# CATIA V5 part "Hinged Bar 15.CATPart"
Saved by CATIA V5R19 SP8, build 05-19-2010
Part number: Hinged Bar 15
Bounding box of the stored display mesh (mm): x -28 to 28, y 589.195 to 1010.805, z 490.09 to 709.91
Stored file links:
  G:\EU_thinkMotion\CFAO_2010\MMS_groupe3\MMS_groupe3\A reprendre\fovide\fovide\Hinged Bar 15.CATPart
  G:\EU_thinkMotion\CFAO_2010\MMS_groupe3\MMS_groupe3\A reprendre\fovide\fovide\fovide.CATProduct
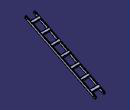
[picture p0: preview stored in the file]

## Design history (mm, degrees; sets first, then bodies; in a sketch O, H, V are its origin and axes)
Parameters
  LENGTH = 50 mm
  LENGTH = 15 mm
Set1
  Plane1: linked copy from another document
  Line1 to Line3: linked copy from another document
Body1 (main body)
  Sketch1 on Plane1, origin (0, 400, 800), H (-1, 0, 0), V (0, -0.8944, 0.4472)
    line L1 (22, -213.6068) -> (28, -213.6068)
    line L2 (28, -213.6068) -> (28, -680.8204)
    line L3 (22, -242.8758) -> (22, -213.6068)
    point P5 (-28, -213.6068)
    line L4 (-28, -213.6068) -> (-22, -213.6068)
    line L5 (-22, -213.6068) -> (-22, -242.8758)
    line L6 (-28, -680.8204) -> (-28, -213.6068)
    reference projected line E1 (150, -223.6068) -> (-150, -223.6068) from Line1
    reference projected line E2 (0, -223.6068) -> (0, -670.8204) from Line2
    reference projected line E3 (0, -223.6068) -> (0, -670.8204) from Line2
    line L7 (-22, -242.8758) -> (22, -242.8758)
    line L8 (28, -680.8204) -> (22, -680.8204)
    point P9 (22, -680.8204)
    line L9 (22, -680.8204) -> (22, -650.0266)
    line L10 (-28, -680.8204) -> (-22, -680.8204)
    point P11 (-22, -680.8204)
    line L11 (-22, -650.0266) -> (22, -650.0266)
    line L12 (-22, -650.0266) -> (-22, -680.8204)
    reference projected line E4 (150, -670.8204) -> (-150, -670.8204) from Line3
    length L1 = 6
    length L4 = 6
    distance L1 E1 = 10
    distance E2 L3 = 22
    distance E3 L5 = 22
    distance L8 E4 = 10
    horizontal: L1 H, L4 H, L7 H, L8 H, L10 H, L11 H
    vertical: L2 V, L3 V, L5 V, L6 V, L9 V, L12 V
    coincidence: P5 L1, P9 L3, P11 L5, L10 L8
  Pad1: profile Sketch1, direction (0, 0.4472, 0.8944), length 8, mirrored extent
  Sketch2 on face of Pad1 from Sketch1.L6, origin (28, 600, 700), H (0, 1, 0), V (0, 0, 1)
    point P1 (0, 0)
    intersected point E1 (0, 0) from Line1
    coincidence: E1 P1
  Hole1: placed by Sketch2, at (28, 600, 700) direction (-1, 0, 0), diameter 10, through (limit type 3)
  Sketch3 on face of Pad1 from Sketch1.L6, origin (28, 1000, 500), H (0, 1, 0), V (0, 0, 1)
    point P1 (0, 0)
    intersected point E1 (0, 0) from Line3
    coincidence: E1 P1
  Hole2: placed by Sketch3, at (28, 1000, 500) direction (-1, 0, 0), diameter 10, through (limit type 3)
  Sketch4 on end face of Pad1, origin (0, 403.5777, 807.1554), H (-1, 0, 0), V (0, -0.8944, 0.4472)
    line L1 (-22, -258.3758) -> (22, -258.3758)
    line L2 (22, -258.3758) -> (22, -308.3758)
    line L3 (22, -308.3758) -> (-22, -308.3758)
    line L4 (-22, -308.3758) -> (-22, -258.3758)
    reference projected line E1 (22, -215.6068) -> (22, -242.8758) from edge [face of Pad1 from Sketch1.L3 | end face of Pad1]
    reference projected line E2 (-22, -242.8758) -> (-22, -215.6068) from edge [face of Pad1 from Sketch1.L5 | end face of Pad1]
    reference projected line E3 (22, -242.8758) -> (-22, -242.8758) from edge [face of Pad1 from Sketch1.L7 | end face of Pad1]
    point P5 (-22, -323.3758)
    line L5 (-22, -323.3758) -> (22, -323.3758)
    line L6 (22, -323.3758) -> (22, -373.3758)
    line L7 (22, -373.3758) -> (-22, -373.3758)
    line L8 (-22, -373.3758) -> (-22, -323.3758)
    point P7 (22, -373.3758)
    line L9 (22, -438.3758) -> (-22, -438.3758)
    line L10 (22, -388.3758) -> (22, -438.3758)
    line L11 (-22, -438.3758) -> (-22, -388.3758)
    point P9 (22, -438.3758)
    line L12 (-22, -388.3758) -> (22, -388.3758)
    point P13 (-22, -453.3758)
    line L13 (-22, -453.3758) -> (22, -453.3758)
    line L14 (22, -503.3758) -> (-22, -503.3758)
    line L15 (22, -453.3758) -> (22, -503.3758)
    line L16 (-22, -503.3758) -> (-22, -453.3758)
    point P14 (22, -503.3758)
    point P17 (-22, -518.3758)
    line L17 (-22, -518.3758) -> (22, -518.3758)
    line L18 (22, -568.3758) -> (-22, -568.3758)
    line L19 (22, -518.3758) -> (22, -568.3758)
    line L20 (-22, -568.3758) -> (-22, -518.3758)
    point P18 (22, -568.3758)
    point P21 (-22, -583.3758)
    line L21 (-22, -583.3758) -> (22, -583.3758)
    line L22 (22, -633.3758) -> (-22, -633.3758)
    line L23 (22, -583.3758) -> (22, -633.3758)
    line L24 (-22, -633.3758) -> (-22, -583.3758)
    point P22 (22, -633.3758)
    distance L1 E3 = 15.5
    length L2 = 50 {= LENGTH}
    distance L5 L3 = 15 {= LENGTH}
    length L6 = 50 {= LENGTH}
    length L10 = 50 {= LENGTH}
    distance L7 L12 = 15 {= LENGTH}
    length L15 = 50 {= LENGTH}
    distance L9 L13 = 15 {= LENGTH}
    length L19 = 50 {= LENGTH}
    distance L14 L17 = 15 {= LENGTH}
    length L23 = 50 {= LENGTH}
    distance L18 L21 = 15 {= LENGTH}
    horizontal: L1 H, L3 H, L5 H, L7 H, L9 H, L13 H, L14 H, L17 H, L18 H, L21 H, L22 H
    vertical: L2 V, L4 V, L6 V, L8 V, L10 V, L11 V, L15 V, L16 V, L19 V, L20 V, L23 V, L24 V
    coincidence: L2 E1, L4 E2, P5 L4, P7 L2, P9 L2, L11 L8, P13 L4, P14 L2, P17 L4, P18 L2, P21 L4, P22 L2
  Pocket1: profile Sketch4, direction (0, -0.4472, -0.8944), through (limit type 6)
  Fillet1: radius 5, on edge [face of Pad1 from Sketch1.L4 | end face of Pad1]; edge [start face of Pad1 | face of Pad1 from Sketch1.L4]; edge [face of Pad1 from Sketch1.L1 | end face of Pad1]; edge [start face of Pad1 | face of Pad1 from Sketch1.L1]; edge [face of Pad1 from Sketch1.L8 | end face of Pad1]; edge [start face of Pad1 | face of Pad1 from Sketch1.L8]; edge [start face of Pad1 | face of Pad1 from Sketch1.L10]; edge [face of Pad1 from Sketch1.L10 | end face of Pad1]
  Fillet2: radius 2, on end face of Pad1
